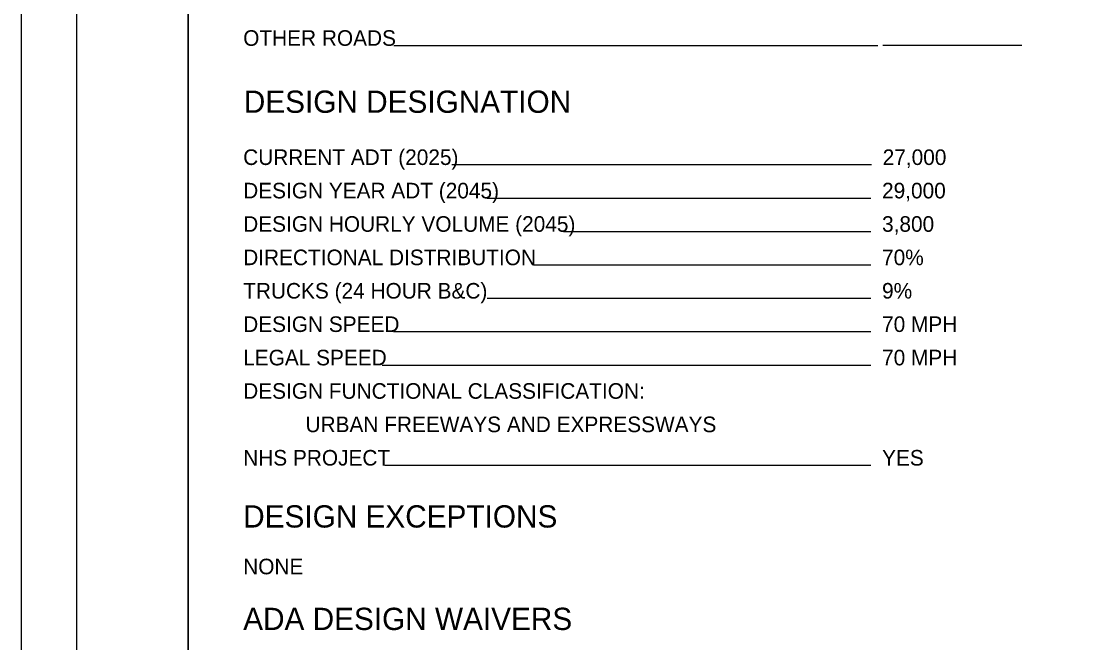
# Model space of a CAD drawing. Extents: x 0 to 34, y 0 to 22.
# Drawn here: x 0 to 9.58, y 5.52 to 11.1 of the extents above; entities that cross this region are included whole.
import ezdxf

# ---------------------------------------------------------------- set-up
doc = ezdxf.new("R2010")
doc.units = 0
for name, color, linetype in [('SH_Border', 7, 'Continuous'), ('SH_Cut_Line', 7, 'Continuous'), ('SH_Data', 7, 'Continuous'), ('SH_Text', 7, 'Continuous')]:
    doc.layers.add(name, color=color, linetype=linetype)

msp = doc.modelspace()

# ---------------------------------------------------------------- linework, layer by layer
at = {"layer": 'SH_Border'}
for points in [[(0.5, 21.5), (1.5, 21.5), (1.5, 0.5), (0.5, 0.5)], [(1.5, 21.5), (33.5, 21.5), (33.5, 0.5), (1.5, 0.5)]]:
    msp.add_lwpolyline(points, close=True, dxfattribs=at)
at = {"layer": 'SH_Cut_Line'}
msp.add_lwpolyline([(0, 0), (34, 0), (34, 22), (0, 22)], close=True, dxfattribs=at)
at = {"layer": 'SH_Data'}
for p, q in [((7.7, 10.8767), (3.3471, 10.8767)), ((8.9924, 10.8782), (7.7424, 10.8782)), ((7.6424, 9.8062), (3.871, 9.8062)), ((7.6368, 9.5062), (4.1885, 9.5062)), ((7.6368, 9.2062), (4.8723, 9.2062)), ((7.6368, 8.9062), (4.6037, 8.9062)), ((7.6368, 8.6062), (4.1885, 8.6062)), ((7.6368, 8.3062), (3.346, 8.3062)), ((7.6368, 8.0062), (3.2422, 8.0062)), ((7.6368, 7.1062), (3.2669, 7.1062))]:
    msp.add_line(p, q, dxfattribs=at)

# ---------------------------------------------------------------- texts
msp.add_text('DESIGN DESIGNATION', height=0.2, dxfattribs=at).set_placement((2, 10.2747))
at = {"layer": 'SH_Text'}
for s, height, p in [('OTHER ROADS', 0.14, (1.9944, 10.8767)), ('CURRENT ADT (2025)', 0.14, (1.9944, 9.8062)), ('27,000', 0.14, (7.7424, 9.8062)), ('DESIGN YEAR ADT (2045)', 0.14, (1.9944, 9.5062)), ('29,000', 0.14, (7.7368, 9.5062)), ('DESIGN HOURLY VOLUME (2045)', 0.14, (1.9944, 9.2062)), ('3,800', 0.14, (7.7368, 9.2062)), ('DIRECTIONAL DISTRIBUTION', 0.14, (1.9944, 8.9062)), ('70%', 0.14, (7.7368, 8.9062)), ('TRUCKS (24 HOUR B&C)', 0.14, (1.9944, 8.6062)), ('9%', 0.14, (7.7368, 8.6062)), ('DESIGN SPEED', 0.14, (1.9944, 8.3062)), ('70 MPH', 0.14, (7.7368, 8.3062)), ('LEGAL SPEED', 0.14, (1.9944, 8.0062)), ('70 MPH', 0.14, (7.7368, 8.0062)), ('DESIGN FUNCTIONAL CLASSIFICATION:', 0.14, (1.9944, 7.7062)), ('URBAN FREEWAYS AND EXPRESSWAYS', 0.14, (2.5544, 7.4062)), ('NHS PROJECT', 0.14, (1.9944, 7.1062)), ('YES', 0.14, (7.7368, 7.1062)), ('DESIGN EXCEPTIONS', 0.2, (1.9944, 6.5494)), ('NONE', 0.14, (1.9944, 6.1294)), ('ADA DESIGN WAIVERS', 0.2, (1.9944, 5.629))]:
    msp.add_text(s, height=height, dxfattribs=at).set_placement(p)

doc.saveas('drawing.dxf')
